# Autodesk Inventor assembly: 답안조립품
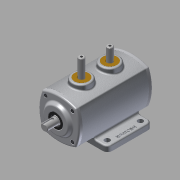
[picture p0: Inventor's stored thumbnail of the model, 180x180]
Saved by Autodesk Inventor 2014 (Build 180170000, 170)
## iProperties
Created: 2015-07
Part Number: 답안조립품
Document SubType Name: Assembly
Designer: Administrator
Mass: 2515.1 g
Surface Area: 1894.51 cm^2
Volume: 719.238 cm^3
Density: 3.4969 g/cm^3
Author: Administrator
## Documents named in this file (12)
- C:\Users\Administrator\Desktop\350727V1003\답안조립품.iam
- C:\Users\Administrator\Desktop\350727V1003\본체.ipt
- C:\Users\Administrator\Desktop\350727V1003\앞커버.ipt
- C:\Users\Administrator\Desktop\350727V1003\뒷커버.ipt
- C:\Users\Administrator\Desktop\350727V1003\오일실.ipt
- C:\Users\Administrator\Desktop\350727V1003\베어링 6203.ipt
- C:\Users\Administrator\Desktop\350727V1003\축.ipt
- C:\Users\Administrator\Desktop\350727V1003\M4-소켓머리.ipt
- C:\Users\Administrator\Desktop\350727V1003\부시.ipt
- C:\Users\Administrator\Desktop\350727V1003\슬라이더.ipt
- C:\Users\Administrator\Desktop\350727V1003\스프링_01 [가변부품].ipt
- C:\Users\Administrator\Desktop\350727V1003\스프링_02 [가변부품].ipt
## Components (11 placed, 3 different names)
1. 7-베어링 6203:2 — 각도:2
2. 8-오일실:1
3. 7-베어링 6203:1 — 각도:1
4. 9-M4-소켓머리:1
5. 9-M4-소켓머리:3
6. 9-M4-소켓머리:4
7. 9-M4-소켓머리:5
8. 9-M4-소켓머리:2
9. 9-M4-소켓머리:6
10. 9-M4-소켓머리:7
11. 9-M4-소켓머리:8
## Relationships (2: Angle 2)
- 각도:1 [Angle]: 7-베어링 6203:1
- 각도:2 [Angle]: 7-베어링 6203:2
